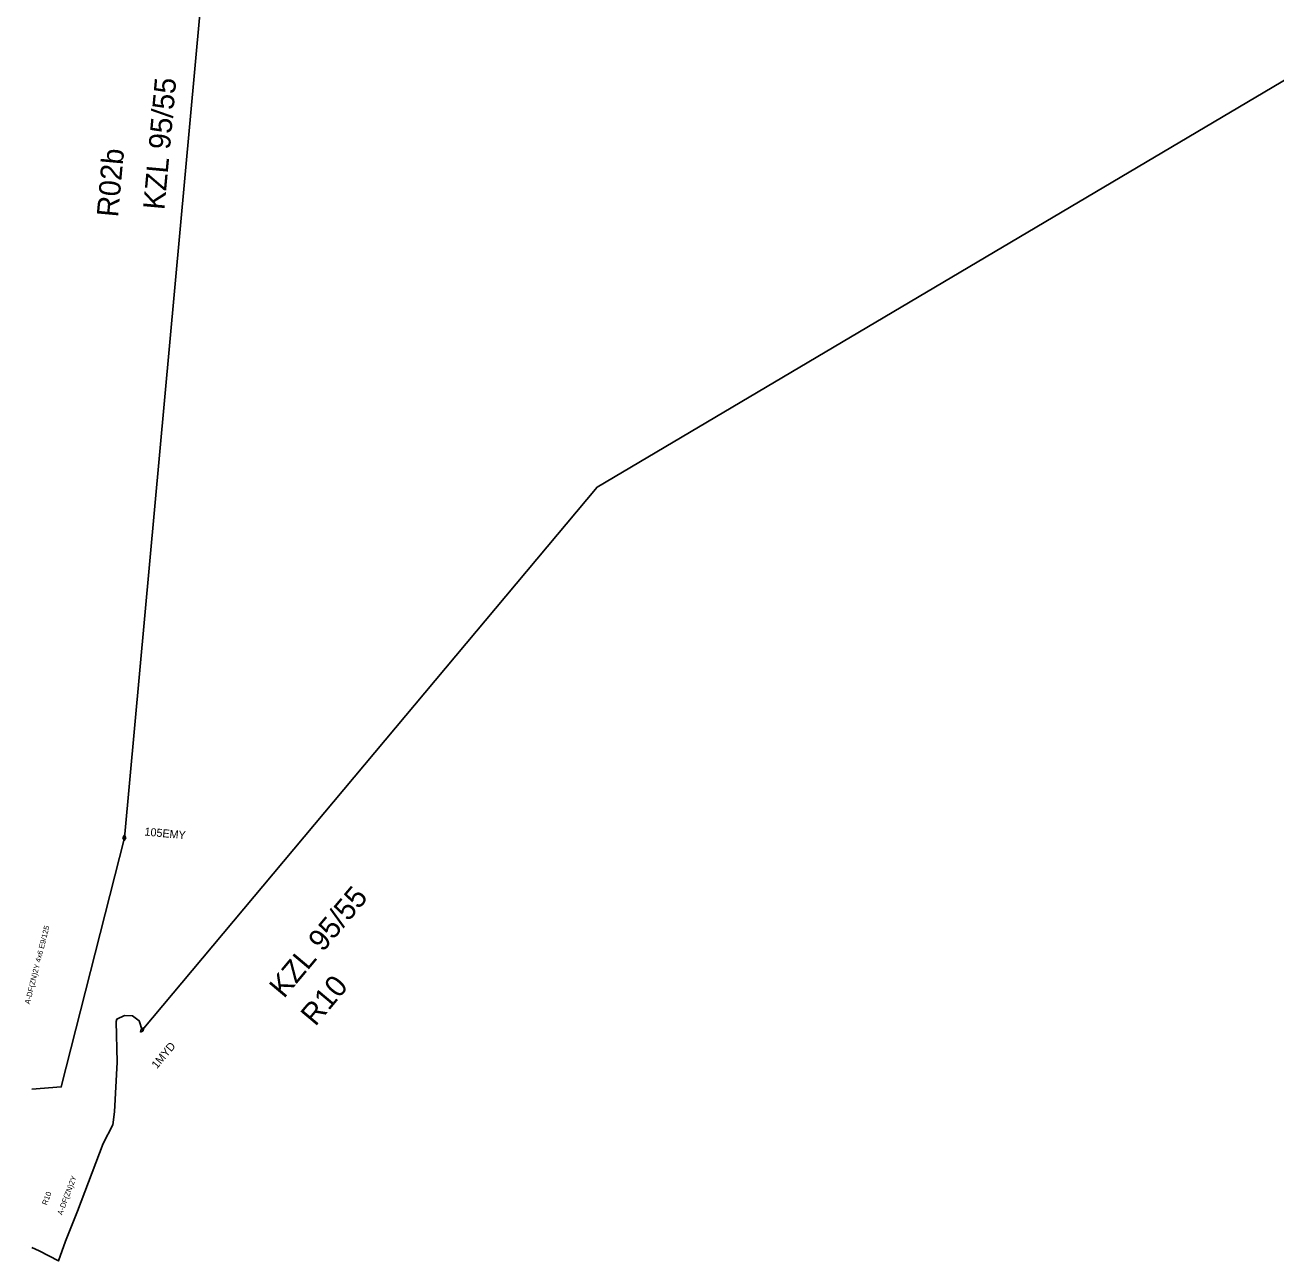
# Model space of a CAD drawing. Extents: x -762501 to -761573, y -1153000 to -1152000.
# Drawn here: x -762501.3 to -762269.2, y -1152713.7 to -1152484.5 of the extents above; entities that cross this region are included whole.
import ezdxf

# ---------------------------------------------------------------- set-up
doc = ezdxf.new("R2010")
doc.units = 0
for name, color, linetype in [('Vrstva 1', 7, 'Continuous'), ('Vrstva 11', 7, 'Continuous'), ('Vrstva 12', 7, 'Continuous'), ('Vrstva 2', 7, 'Continuous'), ('Vrstva 3', 7, 'Continuous'), ('Vrstva 4', 7, 'Continuous'), ('Vrstva 5', 7, 'Continuous')]:
    doc.layers.add(name, color=color, linetype=linetype)

msp = doc.modelspace()

# ---------------------------------------------------------------- linework, layer by layer
at = {"layer": 'Vrstva 1'}
for points in [[(-762483.083, -1152635.223), (-762482.788, -1152634.743)], [(-762482.875, -1152635.739), (-762483.083, -1152635.223)], [(-762482.875, -1152635.739), (-762482.581, -1152635.259)], [(-762482.581, -1152635.259), (-762482.788, -1152634.743)], [(-762479.74, -1152670.733), (-762479.227, -1152670.5)], [(-762479.343, -1152671.044), (-762479.227, -1152670.5)], [(-762479.856, -1152671.277), (-762479.74, -1152670.733)], [(-762479.856, -1152671.277), (-762479.343, -1152671.044)]]:
    msp.add_lwpolyline(points, dxfattribs=at)
at = {"layer": 'Vrstva 11'}
for points in [[(-762432.5, -1152000), (-762455.69, -1152339.16), (-762482.83, -1152635.24)], [(-762479.53, -1152670.89), (-762395.11, -1152570.2), (-761572.86, -1152083.54)]]:
    msp.add_lwpolyline(points, dxfattribs=at)
at = {"layer": 'Vrstva 3'}
for points in [[(-762500, -1152681.82), (-762494.55, -1152681.44), (-762482.83, -1152635.24)], [(-762500, -1152711.24), (-762498.65, -1152711.83), (-762495.07, -1152713.71), (-762493.72, -1152710.03), (-762491.55, -1152704.5), (-762486.76, -1152691.95), (-762484.97, -1152688.44), (-762484.63, -1152686.04), (-762484.14, -1152676.84), (-762484.33, -1152669.29), (-762484.25, -1152668.89), (-762482.81, -1152668.21), (-762481.35, -1152668.26), (-762480.08, -1152669.17), (-762479.53, -1152670.89)]]:
    msp.add_lwpolyline(points, dxfattribs=at)
at = {"layer": 'Vrstva 5'}
for points in [[(-762500, -1152681.82), (-762494.55, -1152681.44), (-762482.83, -1152635.24)], [(-762500, -1152711.24), (-762498.65, -1152711.83), (-762495.07, -1152713.71), (-762493.72, -1152710.03), (-762491.55, -1152704.5), (-762486.76, -1152691.95), (-762484.97, -1152688.44), (-762484.63, -1152686.04), (-762484.14, -1152676.84), (-762484.33, -1152669.29), (-762484.25, -1152668.89), (-762482.81, -1152668.21), (-762481.35, -1152668.26), (-762480.08, -1152669.17), (-762479.53, -1152670.89)]]:
    msp.add_lwpolyline(points, dxfattribs=at)

# ---------------------------------------------------------------- texts
at = {"layer": 'Vrstva 12'}
for s, rotation, p in [('KZL 95/55', 84.76241, (-762475.41, -1152518.89)), ('R02b', 84.76241, (-762484.02, -1152520.24)), ('KZL 95/55', 50.02101, (-762453.23, -1152665.16)), ('R10', 50.02101, (-762447.4, -1152670.34))]:
    msp.add_text(s, height=3.9772, rotation=rotation, dxfattribs=at).set_placement(p)
at = {"layer": 'Vrstva 2'}
for s, rotation, p in [('105EMY ', 354.76241, (-762479.14, -1152634.8)), ('1MYD ', 50.02101, (-762476.79, -1152678.16))]:
    msp.add_text(s, height=1.4914, rotation=rotation, dxfattribs=at).set_placement(p)
at = {"layer": 'Vrstva 4'}
for s, height, rotation, p in [('A-DF(ZN)2Y 4x6 E9/125', 0.99429, 75.76724, (-762500.39, -1152666.17)), ('A-DF(ZN)2Y', 0.9943, 69.10948, (-762494.39, -1152705.27)), ('R10', 0.9943, 69.10948, (-762497.22, -1152703.44))]:
    msp.add_text(s, height=height, rotation=rotation, dxfattribs=at).set_placement(p)

doc.saveas('drawing.dxf')
